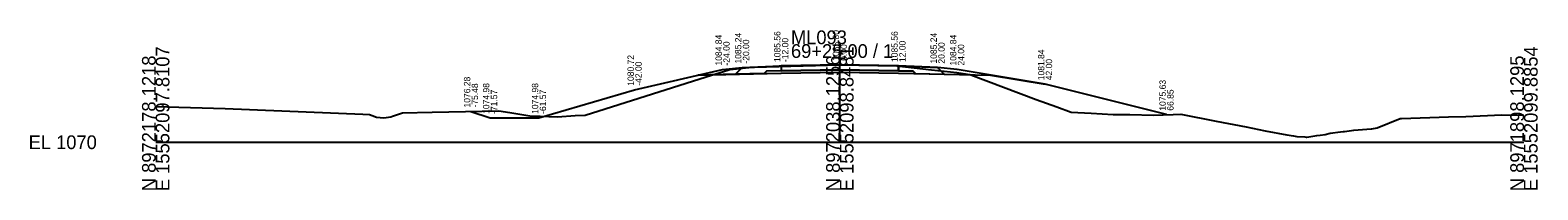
# Model space of a CAD drawing. Extents: x -26 to 14283, y -10 to 28.
# Drawn here: x 4974.3 to 5282.8, y -9.7 to 22.8 of the extents above; entities that cross this region are included whole.
import ezdxf

# ---------------------------------------------------------------- set-up
doc = ezdxf.new("R2010")
doc.units = 0
for name, color, linetype in [('Default', 7, 'Continuous'), ('dsn3DCenterLine', 7, 'Continuous'), ('dsn3DDitchBack', 7, 'Continuous'), ('dsn3DDitchFront', 7, 'Continuous'), ('dsn3DForeSlopeBarnRoofPoint', 7, 'Continuous'), ('dsn3DForeSlopeBreakLine', 7, 'Continuous'), ('dsn3DGroundLineIntercept', 7, 'Continuous'), ('dsn3DPavementTop', 7, 'Continuous'), ('dsn3DShoulderTop', 7, 'Continuous'), ('dsn3DSubgradeBreakLine', 7, 'Continuous'), ('dsn3DSubgradeHingePoint', 7, 'Continuous'), ('dsnGeopakCellCrossSection', 7, 'Continuous'), ('dsnXSEarthwork', 7, 'Continuous'), ('dsnXsExistingGround', 7, 'Continuous'), ('dsnXsPCCPavement', 7, 'Continuous'), ('dsnXsShldrEarthFill', 7, 'Continuous'), ('dsnXsShldrGranular', 7, 'Continuous'), ('dsnXsSideSlopes', 7, 'Continuous'), ('dsnXsSubbase', 7, 'Continuous'), ('dsnXsTextOffsetElevFinGrd', 7, 'Continuous')]:
    doc.layers.add(name, color=color, linetype=linetype)

msp = doc.modelspace()

# ---------------------------------------------------------------- linework, layer by layer
at = {"layer": 'Default'}
for points in [[(5120, 15.24), (5140, 15.8), (5152, 15.56), (5160, 15.24)], [(5111.02, 13.7), (5111.02, 13.7), (5128, 14.06), (5140, 14.3), (5152, 14.06), (5170.84, 13.7), (5182, 11.84)]]:
    msp.add_lwpolyline(points, dxfattribs=at)
at = {"layer": 'dsnGeopakCellCrossSection'}
for p, q in [((5140, 0), (5140, 20)), ((5000, 0), (5140, 0)), ((5140, 0), (5280, 0))]:
    msp.add_line(p, q, dxfattribs=at)
at = {"layer": 'dsnXSEarthwork'}
msp.add_lwpolyline([(5120, 15.24), (5128, 15.56), (5140, 15.8), (5152, 15.56), (5160, 15.24)], dxfattribs=at)
at = {"layer": 'dsnXsExistingGround'}
msp.add_lwpolyline([(5000, 7.27), (5014.21, 6.86), (5042.41, 5.74), (5043.76, 5.67), (5044.82, 5.22), (5044.95, 5.15), (5045.16, 5.13), (5046.7, 4.96), (5048.11, 5.21), (5048.46, 5.29), (5050.33, 5.92), (5050.49, 5.97), (5056.56, 6.11), (5070.23, 6.41), (5072.45, 6.05), (5076.58, 5.38), (5078.65, 5.3), (5082.2, 5.19), (5085.87, 5.43), (5087.88, 5.55), (5112.65, 13.33), (5117.28, 14.78), (5117.55, 14.81), (5121.98, 15.28), (5122.32, 15.3), (5127.58, 15.6), (5128.87, 15.62), (5139.94, 15.79), (5143.89, 15.71), (5151.66, 15.58), (5158.79, 14.76), (5163.92, 14.2), (5166.59, 13.79), (5166.82, 13.75), (5180.16, 8.69), (5184.4, 7.2), (5187.35, 6.12), (5191.42, 5.92), (5195.96, 5.68), (5196.18, 5.69), (5199.37, 5.68), (5204.19, 5.54), (5208.19, 5.68), (5209.81, 5.74), (5217.02, 4.3), (5223.17, 3.12), (5227.03, 2.33), (5231.48, 1.54), (5232.85, 1.32), (5233.54, 1.2), (5235.13, 1.07), (5235.43, 1.04), (5235.55, 1.06), (5237.62, 1.36), (5238.32, 1.44), (5239.3, 1.61), (5240.35, 1.88), (5242.48, 2.1), (5243.05, 2.19), (5243.28, 2.22), (5245.15, 2.46), (5248.74, 2.72), (5248.88, 2.73), (5249.95, 2.94), (5254.64, 4.84), (5254.95, 4.84), (5264.56, 5.19), (5268.11, 5.26), (5275.48, 5.59), (5280, 5.5)], dxfattribs=at)
at = {"layer": 'dsnXsPCCPavement'}
msp.add_lwpolyline([(5128, 15.56), (5128, 15.56), (5128, 14.56), (5128, 14.56), (5128, 14.56), (5140, 14.8), (5152, 14.56), (5152, 14.56), (5152, 14.56), (5152, 15.56), (5152, 15.56), (5140, 15.8), (5128, 15.56)], dxfattribs=at)
at = {"layer": 'dsnXsShldrEarthFill'}
for points in [[(5118.62, 13.87), (5111.02, 13.7)], [(5161.36, 13.89), (5170.84, 13.7)]]:
    msp.add_lwpolyline(points, dxfattribs=at)
at = {"layer": 'dsnXsShldrGranular'}
for points in [[(5120, 15.24), (5128, 15.56), (5128, 14.56), (5128, 14.56), (5125, 14.5), (5125, 14.5), (5124.49, 13.99), (5124.49, 13.99), (5124.49, 13.99), (5118.62, 13.87), (5118.62, 13.87), (5120, 15.24), (5120, 15.24)], [(5160, 15.24), (5152, 15.56), (5152, 14.56), (5152, 14.56), (5155, 14.5), (5155, 14.5), (5155.51, 14), (5155.51, 14), (5161.36, 13.89), (5161.36, 13.89), (5161.36, 13.89), (5160, 15.24), (5160, 15.24)]]:
    msp.add_lwpolyline(points, dxfattribs=at)
at = {"layer": 'dsnXsSideSlopes'}
for points in [[(5064.52, 6.28), (5064.52, 6.28), (5068.43, 4.98), (5068.43, 4.98), (5078.43, 4.98), (5078.43, 4.98), (5098, 10.72), (5116, 14.84), (5116, 14.84), (5116, 14.84), (5120, 15.24)], [(5206.85, 5.63), (5206.85, 5.63), (5182, 11.84), (5182, 11.84), (5164, 14.84), (5164, 14.84), (5160, 15.24)]]:
    msp.add_lwpolyline(points, dxfattribs=at)
at = {"layer": 'dsnXsSubbase'}
msp.add_lwpolyline([(5124.49, 13.99), (5124.49, 13.99), (5124.49, 13.99), (5128, 14.06), (5128, 14.06), (5140, 14.3), (5152, 14.06), (5152, 14.06), (5155.51, 14), (5155.51, 14), (5155.51, 14), (5155, 14.5), (5155, 14.5), (5152, 14.56), (5152, 14.56), (5140, 14.8), (5128, 14.56), (5128, 14.56), (5125, 14.5), (5125, 14.5), (5124.49, 13.99)], dxfattribs=at)

# ---------------------------------------------------------------- texts
msp.add_text('-', height=0.0001).set_placement((5000, 0))
at = {"layer": 'dsn3DCenterLine'}
msp.add_text('X', height=0.00781, dxfattribs=at).set_placement((5140, 15.8))
at = {"layer": 'dsn3DDitchBack'}
msp.add_text('X', height=0.00781, dxfattribs=at).set_placement((5068.43, 4.98))
at = {"layer": 'dsn3DDitchFront'}
msp.add_text('X', height=0.00781, dxfattribs=at).set_placement((5078.43, 4.98))
at = {"layer": 'dsn3DForeSlopeBarnRoofPoint'}
for p in [(5098, 10.72), (5182, 11.84)]:
    msp.add_text('X', height=0.00781, dxfattribs=at).set_placement(p)
at = {"layer": 'dsn3DForeSlopeBreakLine'}
for p in [(5116, 14.84), (5164, 14.84)]:
    msp.add_text('X', height=0.00781, dxfattribs=at).set_placement(p)
at = {"layer": 'dsn3DGroundLineIntercept'}
for p in [(5064.52, 6.28), (5206.84, 5.63)]:
    msp.add_text('X', height=0.00781, dxfattribs=at).set_placement(p)
at = {"layer": 'dsn3DPavementTop'}
for p in [(5128, 15.56), (5152, 15.56)]:
    msp.add_text('X', height=0.00781, dxfattribs=at).set_placement(p)
at = {"layer": 'dsn3DShoulderTop'}
for p in [(5120, 15.24), (5160, 15.24)]:
    msp.add_text('X', height=0.00781, dxfattribs=at).set_placement(p)
at = {"layer": 'dsn3DSubgradeBreakLine'}
for p in [(5128, 14.06), (5140, 14.3), (5152, 14.06)]:
    msp.add_text('X', height=0.00781, dxfattribs=at).set_placement(p)
at = {"layer": 'dsn3DSubgradeHingePoint'}
for p in [(5111.02, 13.7), (5170.83, 13.7)]:
    msp.add_text('X', height=0.00781, dxfattribs=at).set_placement(p)
at = {"layer": 'dsnGeopakCellCrossSection'}
for s, p in [('ML093', (5130, 20)), ('69+25.00 / 1', (5130, 17.2)), ('EL 1070', (4974, -1.4))]:
    msp.add_text(s, height=2.8, dxfattribs=at).set_placement(p)
for s, p in [('E 15552097.8107', (5002.8, -10)), ('E 15552098.8481', (5142.8, -10)), ('E 15552099.8854', (5282.8, -10)), ('N 8972178.1218', (5000, -10)), ('N 8972038.1256', (5140, -10)), ('N 8971898.1295', (5280, -10))]:
    msp.add_text(s, height=2.8, rotation=90, dxfattribs=at).set_placement(p)
at = {"layer": 'dsnXsTextOffsetElevFinGrd'}
for s, p in [('1084.84', (5115.85, 15.64)), ('1085.24', (5119.85, 16.04)), ('1085.56', (5127.85, 16.36)), ('1085.56', (5127.85, 16.36)), ('1085.80', (5139.85, 16.6)), ('1085.56', (5151.85, 16.36)), ('1085.24', (5159.85, 16.04)), ('1084.84', (5163.85, 15.64)), ('-24.00', (5117.45, 15.64)), ('-20.00', (5121.45, 16.04)), ('-12.00', (5129.45, 16.36)), ('-12.00', (5129.45, 16.36)), ('0.00', (5141.45, 16.6)), ('12.00', (5153.45, 16.36)), ('20.00', (5161.45, 16.04)), ('24.00', (5165.45, 15.64)), ('1081.84', (5181.85, 12.64)), ('1080.72', (5097.85, 11.52)), ('-42.00', (5099.45, 11.52)), ('42.00', (5183.45, 12.64)), ('1076.28', (5064.37, 7.08)), ('1075.63', (5206.7, 6.43)), ('1075.63', (5206.7, 6.43)), ('-75.48', (5065.97, 7.08)), ('1074.98', (5068.28, 5.78)), ('-71.57', (5069.88, 5.78)), ('1074.98', (5078.28, 5.78)), ('1074.98', (5078.28, 5.78)), ('-61.57', (5079.88, 5.78)), ('-61.57', (5079.88, 5.78)), ('66.85', (5208.3, 6.43)), ('66.85', (5208.3, 6.43))]:
    msp.add_text(s, height=1.3, rotation=90, dxfattribs=at).set_placement(p)

doc.saveas('drawing.dxf')
